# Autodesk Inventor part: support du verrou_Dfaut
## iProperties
Created: 2007-07
Part Number: support du verrou_Dfaut
Document SubType Name: Modeling
Designer: EF
Density: 1 g/cm^3
Author: EF
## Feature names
1. Base1
